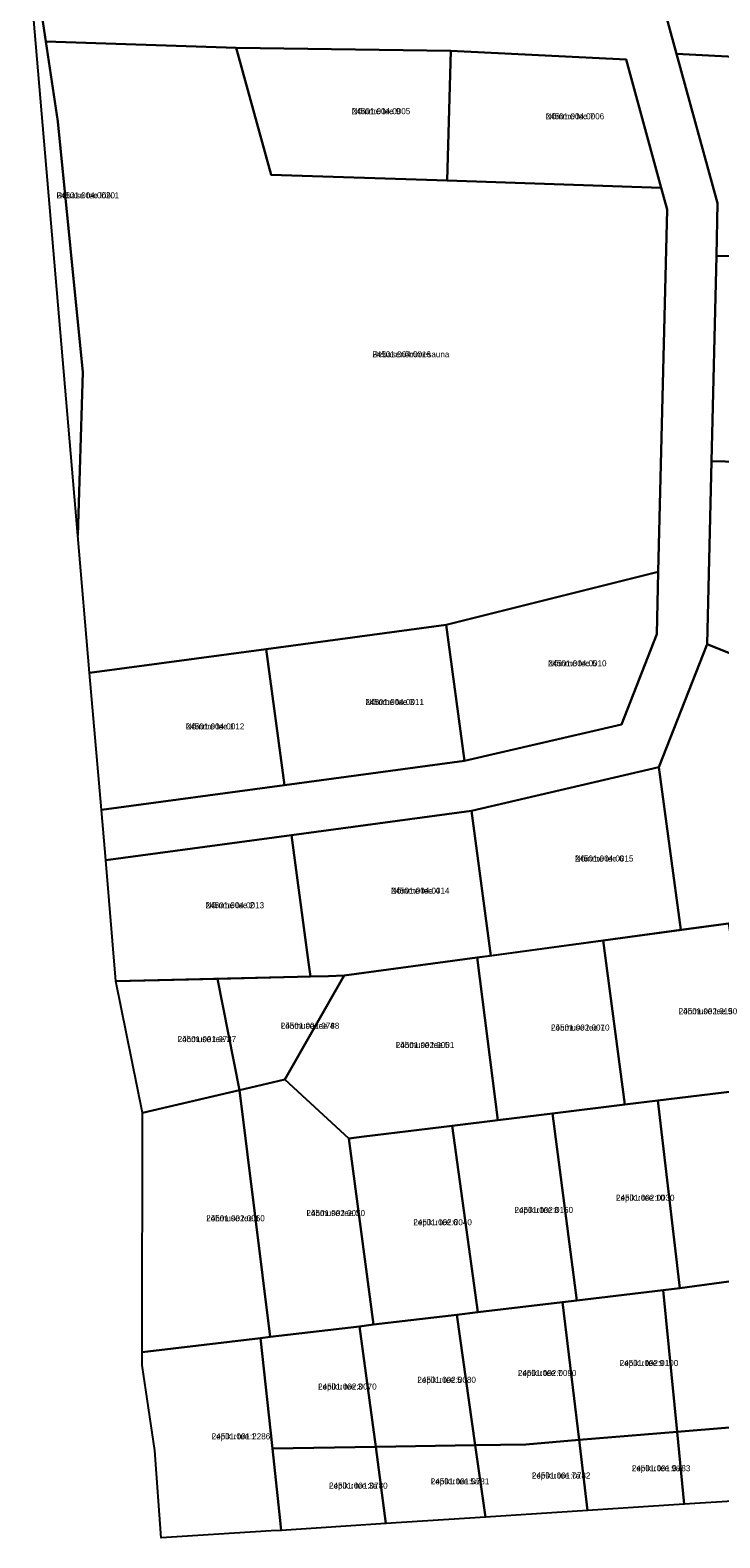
# Model space of a CAD drawing. Extents: x 551291 to 575799, y 6581704 to 6610137.
# Drawn here: x 555726.8 to 555897.6, y 6593566.2 to 6593939.8 of the extents above; entities that cross this region are included whole.
import ezdxf

# ---------------------------------------------------------------- set-up
doc = ezdxf.new("R2010")
doc.units = 0
for name, color, linetype in [('L_AADRESS', 7, 'Continuous'), ('PIIR', 7, 'Continuous'), ('TUNNUS', 7, 'Continuous')]:
    doc.layers.add(name, color=color, linetype=linetype)

msp = doc.modelspace()

# ---------------------------------------------------------------- linework, layer by layer
at = {"layer": 'PIIR'}
for points in [[(555726.78, 6593952.97), (555728.25, 6593952.92), (555730.66, 6593936.95), (555733.62, 6593917.12), (555739.8, 6593855), (555738.62, 6593814.55)], [(555730.66, 6593936.95), (555728.25, 6593952.92), (555882.38, 6593950.62), (555886.94, 6593933.91), (555897.09, 6593896.87), (555896.8, 6593883.85), (555895.56, 6593833), (555894.51, 6593787.64), (555882.51, 6593757.1), (555836.1, 6593746.29), (555791.49, 6593740.3), (555745.52, 6593734.09), (555744.42, 6593746.59), (555789.81, 6593752.7), (555834.42, 6593758.74), (555873.25, 6593767.74), (555882.05, 6593790.13), (555882.4, 6593805.52), (555884.57, 6593895.33), (555883.1, 6593900.72), (555874.4, 6593932.51), (555830.99, 6593934.66), (555777.84, 6593935.39)], [(555886.94, 6593933.91), (555882.38, 6593950.62), (555908.22, 6593950.24), (555911.56, 6593950.19), (555915.05, 6593950.14), (555937.36, 6593949.81), (555964.84, 6593950.63), (555964.83, 6593906.2), (555926.38, 6593907.77), (555920.34, 6593929.84), (555907.58, 6593932.8)], [(555730.66, 6593936.95), (555777.84, 6593935.39), (555786.46, 6593903.95), (555830.11, 6593902.51), (555883.1, 6593900.72), (555884.57, 6593895.33), (555882.4, 6593805.52), (555829.84, 6593792.39), (555785.26, 6593786.38), (555741.52, 6593780.48), (555738.62, 6593814.55), (555739.8, 6593855), (555733.62, 6593917.12)], [(555777.84, 6593935.39), (555830.99, 6593934.66), (555830.11, 6593902.51), (555786.46, 6593903.95)], [(555830.99, 6593934.66), (555874.4, 6593932.51), (555883.1, 6593900.72), (555830.11, 6593902.51)], [(555920.34, 6593929.84), (555926.38, 6593907.77), (555929.81, 6593894.34), (555928.71, 6593883.09), (555896.8, 6593883.85), (555897.09, 6593896.87), (555886.94, 6593933.91), (555907.58, 6593932.8)], [(555928.71, 6593883.09), (555927.36, 6593870.31), (555926.53, 6593832.22), (555895.56, 6593833), (555896.8, 6593883.85)], [(555926.53, 6593832.22), (555926.32, 6593826.48), (555925.17, 6593775.35), (555894.51, 6593787.64), (555895.56, 6593833)], [(555882.4, 6593805.52), (555882.05, 6593790.13), (555873.25, 6593767.74), (555834.42, 6593758.74), (555829.84, 6593792.39)], [(555834.42, 6593758.74), (555789.81, 6593752.7), (555785.26, 6593786.38), (555829.84, 6593792.39)], [(555925.17, 6593775.35), (555935.21, 6593723.2), (555899.81, 6593718.41), (555887.97, 6593716.79), (555882.51, 6593757.1), (555894.51, 6593787.64)], [(555789.81, 6593752.7), (555744.42, 6593746.59), (555741.52, 6593780.48), (555785.26, 6593786.38)], [(555887.97, 6593716.79), (555868.77, 6593714.19), (555840.94, 6593710.42), (555836.1, 6593746.29), (555882.51, 6593757.1)], [(555840.94, 6593710.42), (555837.54, 6593709.96), (555804.58, 6593705.52), (555800.66, 6593705.39), (555796.24, 6593705.28), (555795.77, 6593708.75), (555791.49, 6593740.3), (555836.1, 6593746.29)], [(555796.24, 6593705.28), (555792.98, 6593705.21), (555748.02, 6593704.08), (555745.52, 6593734.09), (555791.49, 6593740.3), (555795.77, 6593708.75)], [(555899.82, 6593718.36), (555906.12, 6593677.43), (555882.26, 6593674.51), (555874.09, 6593673.53), (555868.77, 6593714.19)], [(555837.54, 6593709.96), (555868.77, 6593714.19), (555874.09, 6593673.53), (555856.15, 6593671.34), (555842.68, 6593669.69)], [(555837.54, 6593709.96), (555842.68, 6593669.69), (555831.34, 6593668.27), (555809.56, 6593665.6), (555805.75, 6593665.13), (555789.86, 6593679.74), (555804.58, 6593705.52)], [(555754.61, 6593671.51), (555748.02, 6593704.08), (555773.16, 6593704.71), (555778.62, 6593677.1)], [(555778.62, 6593677.1), (555773.16, 6593704.71), (555792.98, 6593705.21), (555796.24, 6593705.28), (555800.66, 6593705.39), (555804.58, 6593705.52), (555789.86, 6593679.74)], [(555789.86, 6593679.74), (555805.75, 6593665.13), (555811.86, 6593618.99), (555808.36, 6593618.57), (555786.27, 6593615.94), (555778.62, 6593677.1)], [(555754.61, 6593671.51), (555778.62, 6593677.1), (555786.27, 6593615.94), (555783.84, 6593615.64), (555754.52, 6593612.15)], [(555906.12, 6593677.43), (555907.6, 6593677.61), (555913.92, 6593631.49), (555908.34, 6593630.83), (555887.69, 6593628.01), (555882.26, 6593674.51)], [(555842.68, 6593669.69), (555856.15, 6593671.34), (555862.22, 6593624.98), (555858.63, 6593624.55), (555837.67, 6593622.06), (555831.34, 6593668.27)], [(555874.09, 6593673.53), (555882.26, 6593674.51), (555887.69, 6593628.01), (555883.62, 6593627.53), (555862.22, 6593624.98), (555856.15, 6593671.34)], [(555809.56, 6593665.6), (555831.34, 6593668.27), (555837.67, 6593622.06), (555832.47, 6593621.44), (555811.86, 6593618.99), (555805.75, 6593665.13)], [(555883.63, 6593627.53), (555887.69, 6593628.01), (555908.34, 6593630.83), (555913, 6593594.57), (555887.04, 6593592.41)], [(555858.63, 6593624.55), (555862.22, 6593624.98), (555883.62, 6593627.53), (555887.04, 6593592.41), (555862.76, 6593590.41)], [(555832.47, 6593621.44), (555837.67, 6593622.06), (555858.63, 6593624.55), (555862.76, 6593590.41), (555849.57, 6593589.32), (555837.06, 6593589.1)], [(555811.86, 6593618.99), (555832.47, 6593621.44), (555837.06, 6593589.1), (555812.38, 6593588.69), (555808.36, 6593618.57)], [(555754.53, 6593608.93), (555754.52, 6593612.15), (555783.84, 6593615.64), (555786.85, 6593588.26), (555788.73, 6593570.44), (555788.98, 6593568.02), (555786.52, 6593567.87), (555759.25, 6593566.16), (555757.7, 6593587.83)], [(555786.85, 6593588.26), (555783.84, 6593615.64), (555786.27, 6593615.94), (555808.36, 6593618.57), (555812.38, 6593588.69)], [(555888.79, 6593574.47), (555887.04, 6593592.41), (555913, 6593594.57), (555915.36, 6593576.18)], [(555814.93, 6593569.71), (555812.38, 6593588.69), (555837.06, 6593589.1), (555839.59, 6593571.3)], [(555839.59, 6593571.3), (555837.06, 6593589.1), (555849.57, 6593589.32), (555862.76, 6593590.41), (555864.88, 6593572.93)], [(555864.88, 6593572.93), (555862.76, 6593590.41), (555887.04, 6593592.41), (555888.79, 6593574.47)], [(555788.73, 6593570.44), (555786.85, 6593588.26), (555812.38, 6593588.69), (555814.93, 6593569.71), (555788.98, 6593568.02)]]:
    msp.add_lwpolyline(points, close=True, dxfattribs=at)

# ---------------------------------------------------------------- texts
at = {"layer": 'L_AADRESS'}
for s, p in [('Nõmme tee 9', (555806.45, 6593918.95)), ('Nõmme tee 7', (555854.49, 6593917.69)), ('Rebase tee lõik 1', (555733.29, 6593898.1)), ('Rebasenõmmesauna', (555811.56, 6593858.71)), ('Nõmme tee 5', (555855.07, 6593782.13)), ('Nõmme tee 3', (555809.84, 6593772.54)), ('Nõmme tee 1', (555765.33, 6593766.49)), ('Nõmme tee 6', (555861.73, 6593733.76)), ('Nõmme tee 4', (555816.16, 6593725.79)), ('Nõmme tee 2', (555770.23, 6593722.19)), ('Lõhmuse tee 9', (555887.45, 6593695.92)), ('Lõhmuse tee 4', (555788.87, 6593692.31)), ('Lõhmuse tee 7', (555855.82, 6593691.87)), ('Lõhmuse tee 2', (555763.32, 6593689)), ('Lõhmuse tee 5', (555817.36, 6593687.54)), ('Lepiku tee 10', (555871.92, 6593649.7)), ('Lõhmuse tee 1', (555770.4, 6593644.61)), ('Lõhmuse tee 3', (555795.24, 6593645.9)), ('Lepiku tee 6', (555821.71, 6593643.63)), ('Lepiku tee 8', (555846.78, 6593646.67)), ('Lepiku tee 7', (555847.61, 6593606.26)), ('Lepiku tee 9', (555872.84, 6593608.74)), ('Lepiku tee 3', (555798.11, 6593602.9)), ('Lepiku tee 5', (555822.71, 6593604.57)), ('Lepiku tee 1', (555771.75, 6593590.57)), ('Lepiku tee 7a', (555851.08, 6593580.86)), ('Lepiku tee 9a', (555875.84, 6593582.67)), ('Lepiku tee 3a', (555800.83, 6593578.36)), ('Lepiku tee 5a', (555826.03, 6593579.41))]:
    msp.add_text(s, height=1.5, dxfattribs=at).set_placement(p)
at = {"layer": 'TUNNUS'}
for s, p in [('24501:004:0005', (555806.45, 6593918.95)), ('24501:004:0006', (555854.49, 6593917.69)), ('24501:004:0020', (555733.29, 6593898.1)), ('24501:004:0016', (555811.56, 6593858.71)), ('24501:004:0010', (555855.07, 6593782.13)), ('24501:004:0011', (555809.84, 6593772.54)), ('24501:004:0012', (555765.33, 6593766.49)), ('24501:004:0015', (555861.73, 6593733.76)), ('24501:004:0014', (555816.16, 6593725.79)), ('24501:004:0013', (555770.23, 6593722.19)), ('24501:002:0150', (555887.45, 6593695.92)), ('24501:001:0788', (555788.87, 6593692.31)), ('24501:001:0787', (555763.32, 6593689)), ('24501:002:0010', (555855.82, 6593691.87)), ('24501:002:0001', (555817.36, 6593687.54)), ('24501:002:0030', (555871.92, 6593649.7)), ('24501:002:0060', (555770.4, 6593644.61)), ('24501:002:0050', (555795.24, 6593645.9)), ('24501:002:0040', (555821.71, 6593643.63)), ('24501:002:0160', (555846.78, 6593646.67)), ('24501:002:0090', (555847.61, 6593606.26)), ('24501:002:0100', (555872.84, 6593608.74)), ('24501:002:0070', (555798.11, 6593602.9)), ('24501:002:0080', (555822.71, 6593604.57)), ('24501:001:2286', (555771.75, 6593590.57)), ('24501:001:0782', (555851.08, 6593580.86)), ('24501:001:0783', (555875.84, 6593582.67)), ('24501:001:0780', (555800.83, 6593578.36)), ('24501:001:0781', (555826.03, 6593579.41))]:
    msp.add_text(s, height=1.5, dxfattribs=at).set_placement(p)

doc.saveas('drawing.dxf')
